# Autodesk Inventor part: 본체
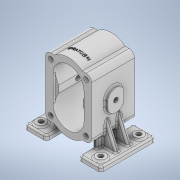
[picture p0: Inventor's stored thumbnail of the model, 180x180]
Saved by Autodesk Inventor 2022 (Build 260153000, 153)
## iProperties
Created: 2023-06
Part Number: 본체
Material: 일반
Document SubType Name: Modeling
Designer: PC-01
Density: 1 g/cm^3
Appearance: 기본값
Author: PC-01
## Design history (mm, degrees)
sketch "스케치1"
  geometry: L1 (-61.534, 0)-(63.223, 0) reference; L2 (0, -90.68)-(0, 96.081) reference; L3 (-42.5, 55)-(-42.5, -55); L4 (-42.5, -55)-(42.5, -55); L5 (42.5, -55)-(42.5, 55); L6 (42.5, 55)-(-42.5, 55); L7 (-22.5, 6.507)-(-22.5, -6.507); L8 (22.5, 6.507)-(22.5, -6.507); L9 (-28.5, 24)-(-28.5, -24); L10 (28.5, 24)-(28.5, -24); A1 r 28.5 centre (0, 24) between (22.5, 6.507) and (-22.5, 6.507); A2 r 28.5 centre (0, -24) between (-22.5, -6.507) and (22.5, -6.507); A3 r 40 centre (0, 24) between (23.723, -8.206) and (-32, 0); A4 r 40 centre (0, -24) between (-32, 0) and (32, 0); 5 further points
  constraints: 16 end point, 14 point on circle, 4 centre point, 3 parallel, 3 vertical, 2 coincident, 2 perpendicular, 2 point on line, 2 tangent, 1 symmetric about line, 3 other
  dimensions: "d0" = 110 distance between parallel lines of L4 L6; "d1" = 85 distance of L5.end L3.start; "d2" = 48 distance of A2.centre A1.centre; "d3" = 57 diameter of A1; "d4" = 80 diameter of A3; "d5" = 80 diameter of A4; "d6" = 57 diameter of A2; "d7" = 45 distance between parallel lines of L8 L7
extrude "돌출1" new body sketch "스케치1" stored distance "d8" = 79; taper "d9" = 0 deg
extrude "돌출2" join sketch "스케치1" stored distance "d10" = 70; taper "d11" = 0 deg
fillet "모깎기1" dims "d12" = 10
node "작업 평면1"
sketch "스케치2"
  geometry: L1 (70, -50)-(30, -50); L2 (30, -50)-(30, 50); L3 (30, 50)-(70, 50); L4 (70, 50)-(70, -50); L5 (-30, -50)-(-70, -50); L6 (-70, -50)-(-70, 50); L7 (-70, 50)-(-30, 50); L8 (-30, 50)-(-30, -50); L9 (102.685, 0)-(-119.489, 0) reference; L10 (0, -59.722)-(0, 81.834) reference; 1 further point
  constraints: 16 end point, 4 parallel, 2 horizontal, 2 perpendicular, 2 point on line, 3 other
  dimensions: "d14" = 40 distance of L1.start L1.end; "d15" = 100 distance of L3.end L1.start; "d16" = 140 distance of L5.end L1.start
extrude "돌출3" join sketch "스케치2" distance "d17" = 9; taper "d18" = 0 deg
sketch "스케치3"
  geometry: L1 (-30, -80)-(-30, -71) reference; L2 (-30, -71)-(-38, -71); L3 (-38, -71)-(-38, -31.856); L4 (-38, -31.856)-(-30, -31.856); L5 (-30, -31.856)-(-30, -71); L6 (70, -71)-(30, -71) reference; L7 (30, -71)-(38, -71); L8 (38, -71)-(38, -35.229); L9 (38, -35.229)-(30, -35.229); L10 (30, -35.229)-(30, -71); 2 further points
  constraints: 16 end point, 4 parallel, 2 horizontal, 2 perpendicular
  dimensions: "d19" = 8 distance of L3.end L4.end; "d20" = 8 distance of L8.end L9.end; "d21" = 39.14441 distance of L2.end L3.end; "d22" = 35.77147 distance of L7.end L8.end
extrude "돌출4" join sketch "스케치3" stored distance "d23" = 50; taper "d24" = 0 deg
sketch "스케치4"
  geometry: L1 (-100.487, 0)-(98.414, 0) reference; L2 (0, 72.936)-(0, -71.25) reference; C1 r 9 at (-55, 35); C2 r 9 at (-55, -35); C3 r 9 at (55, 35); C4 r 9 at (55, -35); 1 further point
  constraints: 4 centre point, 4 symmetric about line
  dimensions: "d25" = 18 diameter of C1; "d26" = 70 distance of C2.centre C1.centre; "d27" = 110 distance of C3.centre C1.centre; "d28" = 18 diameter of C3; "d29" = 18 diameter of C2; "d30" = 18 diameter of C4
extrude "돌출5" join sketch "스케치4" distance "d31" = 3; taper "d32" = 0 deg
fillet "모깎기2" dims "d33" = 5
fillet "모깎기3" dims "d34" = 3
fillet "모깎기4" dims "d35" = 3
sketch "스케치5"
  geometry: C1 r 9 at (0, 0) reference; C2 r 9 at (0, -70) reference; C3 r 9 at (-110, -70) reference; C4 r 9 at (-110, 0) reference; 5 further points
  constraints: 4 coincident
hole "구멍1" sketch "스케치5" at (0, 0), (0, -70), (-110, -70), (-110, 0) diameter "d36" = 9; stored, may be unused: countersink angle "d40" = 90 deg, drill point angle "d42" = 118 deg; dims "d37" = 6, "d38" = 4, "d39" = 2, "d41" = 8
node "작업 평면2"
sketch "스케치6"
  geometry: L1 (42.5, -45)-(42.5, 45) reference; L2 (42.5, -25.061)-(62, -71); L3 (70, -74)-(70, -80) reference; L4 (33, -71)-(38, -71) reference; L5 (38, -71)-(70, -71); 1 further point
  constraints: 4 end point, 2 point on line, 1 horizontal
  dimensions: "d44" = 23 deg angle of L2 L3; "d45" = 8 distance from line of L3 L2.end
feature "리브1" sketch "스케치6" dims "d46" = 1, "d47" = 7, "d48" = 0, "d49" = 0, "d50" = 1, "d51" = 1
sketch "스케치7"
  geometry: L1 (0, -108.8)-(0, 92.8) reference; L2 (-98, 0)-(98, 0) reference; C1 r 4.5 at (-32.5, 45); C2 r 4.5 at (-32.5, -45); C3 r 4.5 at (32.5, -45); C4 r 4.5 at (32.5, 45); 1 further point
  constraints: 4 centre point, 2 symmetric about line
  dimensions: "d52" = 9 diameter of C1; "d53" = 9 diameter of C4; "d54" = 9 diameter of C3; "d55" = 9 diameter of C2; "d57" = 65 distance of C3.centre C2.centre; "d58" = 90 distance of C2.centre C1.centre; "d59" = 65 distance of C4.centre C1.centre; "d60" = 45 distance from line of L2 C1.centre
extrude "돌출6" cut sketch "스케치7" distance "d61" = 79; taper "d62" = 0 deg
fillet "모깎기5" dims "d63" = 3
sketch "스케치8"
  geometry: L1 (-39.5, 65)-(-39.5, 25); L2 (-54.5, 50)-(-54.5, 40); L3 (-24.5, 40)-(-24.5, 50); L4 (-84.5, -35)-(5.5, -35) reference; L5 (-79, 0)-(-79, 90) reference; A1 r 15 centre (-39.5, 50) between (-24.5, 50) and (-54.5, 50); A2 r 15 centre (-39.5, 40) between (-54.5, 40) and (-24.5, 40); 2 further points
  constraints: 8 end point, 6 point on circle, 4 tangent, 2 centre point, 2 point on line, 1 midpoint, 1 parallel, 1 vertical
  dimensions: "d64" = 80 distance from line of L4 point (-39.5, 45); "d65" = 39.5 distance from line of L5 point (-39.5, 45); "d66" = 10 distance of A2.centre A1.centre; "d67" = 30 distance between parallel lines of L3 L2
extrude "돌출7" join sketch "스케치8" distance "d68" = 5; taper "d69" = 0 deg
sketch "스케치9"
  geometry: 1 further point
hole "구멍2" sketch "스케치9" at (-39.5, 45) diameter "d70" = 8.376; stored, may be unused: countersink angle "d74" = 82 deg, drill point angle "d76" = 118 deg; dims "d71" = 12.5, "d72" = 3.023, "d73" = 4.775, "d75" = 8
fillet "모깎기6" dims "d77" = 3
node "작업 평면3"
sketch "스케치10"
  geometry: L1 (98, 0)-(-98, 0) reference; L2 (0, -70)-(0, 70) reference; 2 further points
  constraints: 1 point on line, 1 other
  dimensions: "d79" = 20 distance from line of L1 point (0, 20)
feature "엠보싱1" sketch "스케치10" dims "d10" = 70, "d11" = 0, "d80" = 0.5, "d81" = 0
fillet "모깎기7" dims "d82" = 3
node "솔리드1"
mirror "미러1"
mirror "미러2"
mirror "미러3"
feature "A9D066F2-1C7D-4E18-AEED-F7BC21143FA4" dims "d70" = 8.376, "d71" = 12.5, "d72" = 3.023, "d73" = 4.775, "d74" = 82 deg, "d75" = 8, "d76" = 118 deg
other parameters: "d43" = 11
